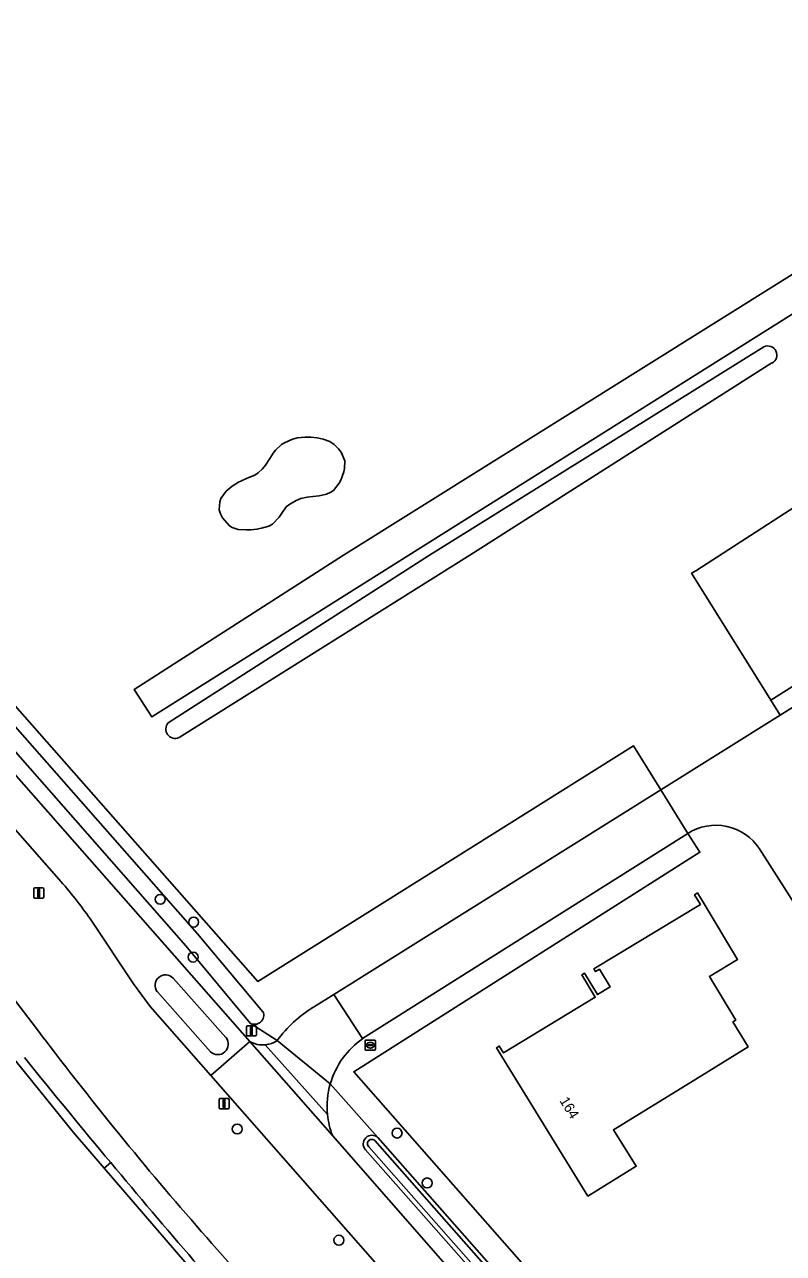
# Model space of a CAD drawing. Extents: x 156061 to 157804, y 383437 to 385640.
# Drawn here: x 157310.1 to 157384.8, y 384181.3 to 384302.2 of the extents above; entities that cross this region are included whole.
import ezdxf

# ---------------------------------------------------------------- set-up
doc = ezdxf.new("R2010")
doc.units = 0
for name, color, linetype in [('IMGEO_Berm_groen', 7, 'Continuous'), ('IMGEO_Boom', 7, 'Continuous'), ('IMGEO_Fietspad_gesloten', 7, 'Continuous'), ('IMGEO_Groenvoorziening', 7, 'Continuous'), ('IMGEO_Hek', 7, 'Continuous'), ('IMGEO_Lichtmast', 7, 'Continuous'), ('IMGEO_Oever', 7, 'Continuous'), ('IMGEO_Pand', 7, 'Continuous'), ('IMGEO_Pand_nummerreeks', 7, 'Continuous'), ('IMGEO_Parkeervlak_open', 7, 'Continuous'), ('IMGEO_Rijbaan_lokaal_gesloten', 7, 'Continuous'), ('IMGEO_Rijbaan_lokaal_open', 7, 'Continuous'), ('IMGEO_Rioolput', 7, 'Continuous'), ('IMGEO_Terreindeel_zand', 7, 'Continuous'), ('IMGEO_Verkeersbordpaal', 7, 'Continuous'), ('IMGEO_Verkeerseiland_open', 7, 'Continuous'), ('IMGEO_Voetpad_gesloten', 7, 'Continuous'), ('IMGEO_Waterloop', 7, 'Continuous')]:
    doc.layers.add(name, color=color, linetype=linetype)

msp = doc.modelspace()

# ---------------------------------------------------------------- linework, layer by layer
at = {"layer": 'IMGEO_Berm_groen'}
for points in [[(157236.85, 384312.33), (157218.46, 384333.49), (157218.41, 384333.56), (157168.13, 384391.67), (157166.48, 384390.53), (157253.43, 384291.77), (157290.16, 384250), (157332.28, 384202.11)], [(157313.49, 384218.11), (157285.45, 384250), (157250.85, 384289.34), (157163.6, 384388.4), (157154.3, 384381.75), (157154.84, 384381.16), (157155.5, 384381.77), (157245.11, 384280.12), (157271.96, 384250), (157283.55, 384237)], [(157334.99, 384202.22), (157332.31, 384203.93), (157326, 384211.55), (157292.2, 384250), (157280.67, 384263.01), (157263.72, 384282.59), (157236.85, 384312.33)], [(157342.96, 384182.28), (157328.46, 384198.78), (157322.49, 384205.56), (157320.85, 384207.79), (157316.61, 384214.17)], [(157344.9, 384192.66), (157340.2, 384197.97)], [(157340.41, 384192.86), (157351.29, 384180.48), (157461.84, 384054.56), (157463.91, 384056.38), (157463.38, 384056.98), (157462.83, 384056.5), (157343.68, 384191.47)], [(157318.6, 384190.2), (157317.96, 384189.64), (157344.19, 384159.18), (157364.55, 384136), (157393.61, 384102.92), (157399.11, 384096.66), (157446.05, 384043.69), (157456.41, 384032.18), (157483.79, 384000), (157500, 383980.87), (157519.27, 383957.9), (157520.38, 383958.3), (157500, 383982.12), (157484.69, 384000), (157449.42, 384041.22), (157450.46, 384042.19), (157447.97, 384045.05), (157446.91, 384044.08), (157389.32, 384108.91), (157390.82, 384110.23), (157391.84, 384111.13), (157448.89, 384045.9), (157456.76, 384052.82), (157342.96, 384182.28)]]:
    msp.add_lwpolyline(points, dxfattribs=at)
for centre, radius, start, end in [((156899.34, 383891.57), 516.66, 36.9691, 41.9576), ((157282.68, 384190.52), 41.35, 34.8854, 41.8577), ((157602.88, 384423.61), 365.4, 217.2792, 219.3769), ((157333.54, 384204.41), 2.62, 241.3507, 275.9719), ((157333.54, 384204.41), 2.63, 276.0213, 303.5695), ((157348.05, 384195.74), 8.16, 164.1263, 185.543), ((157348.05, 384195.72), 8.15, 185.4292, 200.5441), ((157344.3, 384192.04), 0.853, 45.9281, 222.4567), ((157599.37, 384420.91), 360.98, 219.399, 223.387), ((157895.42, 384671.13), 751.01, 219.81993, 221.75138)]:
    msp.add_arc(centre, radius, start, end, dxfattribs=at)
at = {"layer": 'IMGEO_Boom'}
for centre in [(157323.47, 384216.12), (157326.76, 384213.88), (157326.71, 384210.43), (157331.05, 384193.51), (157346.78, 384193.11), (157349.74, 384188.2), (157341.05, 384182.56)]:
    msp.add_circle(centre, 0.489, dxfattribs=at)
at = {"layer": 'IMGEO_Fietspad_gesloten'}
for points in [[(156945.58, 384638.24), (156948.92, 384634.34), (156956.8, 384625), (156966.54, 384613.57), (156977.24, 384601.18), (156992.9, 384582.99), (157000, 384574.89), (157056.89, 384509.94), (157058.63, 384507.87), (157065.54, 384500), (157136.46, 384419.32), (157161.96, 384390.33), (157163.6, 384388.4), (157250.85, 384289.34), (157285.45, 384250), (157313.49, 384218.11)], [(157316.61, 384214.17), (157320.85, 384207.79), (157322.49, 384205.56), (157328.46, 384198.78), (157332.28, 384202.11), (157290.16, 384250), (157253.43, 384291.77), (157166.48, 384390.53), (157164.88, 384392.32), (157139.19, 384421.58)], [(157324.75, 384208.36), (157329.94, 384202.51)], [(157328.41, 384201.12), (157323.19, 384207.02)]]:
    msp.add_lwpolyline(points, dxfattribs=at)
for centre, radius, start, end in [((157282.68, 384190.52), 41.35, 34.8854, 41.8577), ((157323.99, 384207.66), 1.03, 42.9772, 218.4553), ((157329.13, 384201.87), 1.04, 226.0226, 38.4206)]:
    msp.add_arc(centre, radius, start, end, dxfattribs=at)
at = {"layer": 'IMGEO_Groenvoorziening'}
for points in [[(157148.09, 384418.78), (157168.34, 384395.15), (157168.77, 384395.5), (157170.61, 384393.4), (157170.15, 384393.08), (157199.06, 384360.03), (157296.11, 384250), (157333.07, 384208.04), (157370.06, 384231.22), (157372.73, 384226.9), (157384.48, 384234.26), (157383.56, 384235.74), (157375.77, 384248.22), (157376.17, 384248.48), (157394.08, 384260.05), (157409.63, 384270.1), (157417.93, 384257.27), (157401.72, 384247.12), (157402.65, 384245.64), (157409.61, 384250), (157420.5, 384257)], [(157338.54, 384205.49), (157340.57, 384206.76), (157372.73, 384226.9), (157370.06, 384231.22), (157333.07, 384208.04), (157296.11, 384250), (157199.06, 384360.03), (157170.15, 384393.08), (157168.15, 384391.68), (157168.13, 384391.67), (157218.41, 384333.56)], [(157281.33, 384234.83), (157268.18, 384250), (157243.45, 384278.53), (157154.04, 384380.42), (157154.84, 384381.16), (157154.3, 384381.75), (157152.75, 384380.64), (157157.1, 384375.67), (157214.42, 384310.24), (157233.65, 384288.31), (157235.49, 384286.21), (157267.06, 384250), (157294.3, 384218.6), (157310.23, 384198.96), (157314.94, 384193.15), (157317.96, 384189.64), (157318.6, 384190.2)], [(157219.37, 384334.3), (157227.36, 384325.53), (157240.21, 384310.93), (157250.68, 384299.53), (157286.73, 384258.96), (157294.33, 384250), (157327.15, 384212.74), (157333.58, 384205.06)], [(157422.28, 384264.72), (157416.27, 384274.39), (157438.11, 384288.09), (157430, 384300.64), (157429.54, 384301.35), (157347.95, 384250), (157322.66, 384234.08), (157320.89, 384236.78), (157341.5, 384250), (157450.86, 384318.47), (157453.06, 384323.75), (157457.3, 384326.36)], [(157375.38, 384222.59), (157376.59, 384220.76), (157342.51, 384199.14), (157412.58, 384119.43), (157466.22, 384058.41), (157468.2, 384056.16), (157486.53, 384035.35), (157490.12, 384031.28), (157495.9, 384024.71), (157497.66, 384025.67), (157500, 384027.19), (157642, 384119.41), (157643.26, 384117.4), (157752.8, 384188.65), (157752.54, 384194.33), (157751.65, 384205.4), (157750.08, 384220.37), (157749.32, 384226.2), (157748.06, 384232.65), (157745.14, 384247.49), (157743.64, 384254.59), (157738.42, 384274.55), (157728.47, 384313.42)], [(157435.58, 384300.77), (157435.68, 384298.54), (157441.16, 384290.01), (157442.6, 384290.91), (157453.76, 384273.49), (157468.36, 384250), (157480.13, 384231.06), (157405.83, 384184.39), (157382.46, 384221.08)], [(157446.05, 384043.69), (157399.11, 384096.66), (157393.61, 384102.92), (157364.55, 384136), (157344.19, 384159.18), (157317.96, 384189.64), (157314.94, 384193.15), (157310.23, 384198.96), (157294.3, 384218.6), (157267.06, 384250), (157235.49, 384286.21)], [(157324.26, 384233.49), (157349.96, 384250), (157382.88, 384270.52)], [(157383.67, 384268.93), (157353.95, 384250), (157325.32, 384232.04)], [(157340.2, 384197.97), (157344.9, 384192.66), (157463.98, 384057.5), (157463.38, 384056.98), (157463.91, 384056.38), (157466.22, 384058.41), (157412.58, 384119.43), (157342.51, 384199.14), (157376.59, 384220.76), (157375.38, 384222.59), (157343.39, 384202.41)], [(157332.31, 384203.93), (157334.99, 384202.22)]]:
    msp.add_lwpolyline(points, dxfattribs=at)
for points in [[(157332.02, 384257.58), (157332.77, 384257.88), (157333.1, 384258.1), (157333.55, 384258.52), (157333.83, 384258.88), (157334.25, 384259.52), (157334.57, 384260.04), (157334.81, 384260.36), (157335.41, 384260.9), (157335.69, 384261.08), (157336.5, 384261.43), (157336.99, 384261.55), (157337.69, 384261.63), (157338.3, 384261.63), (157338.9, 384261.57), (157339.51, 384261.44), (157340.15, 384261.19), (157340.58, 384260.91), (157341.03, 384260.48), (157341.27, 384260.16), (157341.64, 384259.28), (157341.6, 384258.55), (157341.53, 384258.22), (157341.23, 384257.39), (157341.07, 384257.09), (157340.51, 384256.38), (157340.26, 384256.21), (157339.82, 384256.02), (157339.1, 384255.85), (157338.5, 384255.78), (157337.92, 384255.71), (157337.31, 384255.57), (157336.84, 384255.39), (157336.21, 384255.04), (157335.88, 384254.76), (157335.43, 384254.13), (157335.19, 384253.76), (157334.52, 384253.07), (157334.16, 384252.87), (157333.45, 384252.65), (157332.98, 384252.56), (157332.38, 384252.5), (157331.93, 384252.49), (157331.14, 384252.55), (157330.55, 384252.73), (157330.28, 384252.88), (157329.59, 384253.69), (157329.39, 384254.08), (157329.27, 384254.46), (157329.33, 384255.27), (157329.45, 384255.57), (157329.97, 384256.3), (157330.55, 384256.8), (157331.17, 384257.2), (157331.46, 384257.34)], [(157377.52, 384208.52), (157380.11, 384204.23), (157379.83, 384204.05), (157381.32, 384201.59), (157375.67, 384198.1), (157368.09, 384193.43), (157370.31, 384189.84), (157365.56, 384186.91), (157356.56, 384201.5), (157356.84, 384201.67), (157357.24, 384201.01), (157366.28, 384206.48), (157364.95, 384208.68), (157365.23, 384208.85), (157366.5, 384206.75), (157367.74, 384207.5), (157366.7, 384209.24), (157366.32, 384209.01), (157366.15, 384209.29), (157376.63, 384215.62), (157376.06, 384216.58), (157376.34, 384216.75), (157376.99, 384215.67), (157380.29, 384210.2)]]:
    msp.add_lwpolyline(points, close=True, dxfattribs=at)
for centre, radius, start, end in [((157383.27, 384269.72), 0.888, 296.1463, 116.0599), ((157324.94, 384232.88), 0.919, 138.349, 294.001), ((157378.16, 384218.3), 5.12, 32.8794, 122.899), ((157344.97, 384194.97), 12.34, 121.4303, 143.9831), ((157332.76, 384204.71), 0.895, 239.575, 23.5188), ((157348.15, 384195.63), 8.28, 125.0321, 163.6151), ((157900.4, 384675.33), 757.53, 218.81105, 219.82262)]:
    msp.add_arc(centre, radius, start, end, dxfattribs=at)
at = {"layer": 'IMGEO_Hek'}
for points in [[(157372.73, 384226.9), (157370.06, 384231.22), (157333.07, 384208.04), (157296.11, 384250)], [(157375.38, 384222.59), (157372.73, 384226.9)], [(157376.59, 384220.76), (157342.51, 384199.14), (157412.58, 384119.43), (157466.22, 384058.41)]]:
    msp.add_lwpolyline(points, dxfattribs=at)
at = {"layer": 'IMGEO_Lichtmast'}
for p, q in [((157311.02, 384216.34), (157311.02, 384217.14)), ((157311.02, 384217.14), (157311.02, 384216.34)), ((157311.12, 384217.24), (157311.9, 384217.24)), ((157311.9, 384217.24), (157311.12, 384217.24)), ((157311.9, 384216.24), (157311.12, 384216.24)), ((157311.12, 384216.24), (157311.9, 384216.24)), ((157312, 384217.14), (157312, 384216.34)), ((157312, 384216.34), (157312, 384217.14)), ((157329.26, 384195.6), (157329.26, 384196.4)), ((157329.26, 384196.4), (157329.26, 384195.6)), ((157329.36, 384196.5), (157330.15, 384196.5)), ((157330.15, 384196.5), (157329.36, 384196.5)), ((157330.25, 384196.4), (157330.25, 384195.6)), ((157330.25, 384195.6), (157330.25, 384196.4)), ((157330.15, 384195.5), (157329.36, 384195.5)), ((157329.36, 384195.5), (157330.15, 384195.5))]:
    msp.add_line(p, q, dxfattribs=at)
for points in [[(157311.43, 384217.12), (157311.59, 384217.12), (157311.59, 384216.37), (157311.43, 384216.37), (157311.43, 384217.12)], [(157329.68, 384196.38), (157329.83, 384196.38), (157329.83, 384195.63), (157329.68, 384195.63), (157329.68, 384196.38)]]:
    msp.add_lwpolyline(points, dxfattribs=at)
for centre, start, end in [((157311.12, 384217.14), 90, 180), ((157311.12, 384217.14), 90, 180), ((157311.12, 384216.34), 180, 270), ((157311.12, 384216.34), 180, 270), ((157311.9, 384217.14), 0, 90), ((157311.9, 384217.14), 360, 90), ((157311.9, 384216.34), 270, 0), ((157311.9, 384216.34), 270, 0), ((157329.36, 384196.4), 90, 180), ((157329.36, 384196.4), 90, 180), ((157329.36, 384195.6), 180, 270), ((157329.36, 384195.6), 180, 270), ((157330.15, 384196.4), 0, 90), ((157330.15, 384196.4), 360, 90), ((157330.15, 384195.6), 270, 0), ((157330.15, 384195.6), 270, 0)]:
    msp.add_arc(centre, 0.1, start, end, dxfattribs=at)
at = {"layer": 'IMGEO_Oever'}
for points in [[(157343.68, 384191.47), (157462.83, 384056.5), (157463.38, 384056.98), (157463.98, 384057.5), (157344.9, 384192.66)], [(157344.59, 384192.37), (157463.38, 384057.54), (157463.1, 384057.3), (157462.87, 384057.1), (157385.2, 384145.03), (157343.99, 384191.76)]]:
    msp.add_lwpolyline(points, dxfattribs=at)
for centre, radius, start, end in [((157344.3, 384192.04), 0.853, 45.9281, 222.4567), ((157344.29, 384192.06), 0.429, 45.2195, 225.3478)]:
    msp.add_arc(centre, radius, start, end, dxfattribs=at)
at = {"layer": 'IMGEO_Pand'}
msp.add_lwpolyline([(157379.83, 384204.05), (157380.11, 384204.23), (157377.52, 384208.52), (157380.29, 384210.2), (157376.99, 384215.67), (157376.34, 384216.75), (157376.06, 384216.58), (157376.63, 384215.62), (157366.15, 384209.29), (157366.32, 384209.01), (157366.7, 384209.24), (157367.74, 384207.5), (157366.5, 384206.75), (157365.23, 384208.85), (157364.95, 384208.68), (157366.28, 384206.48), (157357.24, 384201.01), (157356.84, 384201.67), (157356.56, 384201.5), (157365.56, 384186.91), (157370.31, 384189.84), (157368.09, 384193.43), (157375.67, 384198.1), (157381.32, 384201.59)], close=True, dxfattribs=at)
at = {"layer": 'IMGEO_Parkeervlak_open'}
for points in [[(157382.46, 384221.08), (157405.83, 384184.39), (157480.13, 384231.06), (157468.36, 384250), (157453.76, 384273.49)], [(157420.5, 384257), (157409.61, 384250), (157402.65, 384245.64), (157401.03, 384244.62), (157388.51, 384236.78), (157384.48, 384234.26), (157372.73, 384226.9), (157375.38, 384222.59)]]:
    msp.add_lwpolyline(points, dxfattribs=at)
msp.add_lwpolyline([(157383.56, 384235.74), (157387.58, 384238.26), (157400.1, 384246.1), (157401.72, 384247.12), (157417.93, 384257.27), (157409.63, 384270.1), (157394.08, 384260.05), (157376.17, 384248.48), (157375.77, 384248.22)], close=True, dxfattribs=at)
msp.add_arc((157378.16, 384218.3), 5.12, 32.8794, 122.899, dxfattribs=at)
at = {"layer": 'IMGEO_Rijbaan_lokaal_gesloten'}
msp.add_lwpolyline([(157461.84, 384054.56), (157351.29, 384180.48), (157340.41, 384192.86), (157332.28, 384202.11), (157328.46, 384198.78), (157342.96, 384182.28), (157456.76, 384052.82)], dxfattribs=at)
at = {"layer": 'IMGEO_Rijbaan_lokaal_open'}
for points in [[(157457.3, 384326.36), (157453.06, 384323.75), (157450.86, 384318.47), (157341.5, 384250), (157320.89, 384236.78), (157322.66, 384234.08), (157347.95, 384250), (157429.54, 384301.35), (157430, 384300.64), (157436.8, 384305.03), (157437.24, 384305.85), (157437.84, 384306.57), (157456.79, 384318.5), (157458.11, 384316.49), (157462.66, 384309.61), (157468.04, 384313.11), (157465.07, 384317.8)], [(157343.39, 384202.41), (157340.57, 384206.76), (157338.54, 384205.49)], [(157332.28, 384202.11), (157340.41, 384192.86)], [(157333.81, 384201.8), (157339.93, 384194.95)], [(157339.93, 384194.95), (157333.81, 384201.8)], [(157334.99, 384202.22), (157340.2, 384197.97)], [(157340.2, 384197.97), (157334.99, 384202.22)]]:
    msp.add_lwpolyline(points, dxfattribs=at)
msp.add_lwpolyline([(157340.57, 384206.76), (157343.39, 384202.41), (157375.38, 384222.59), (157372.73, 384226.9)], close=True, dxfattribs=at)
for centre, radius, start, end in [((157344.97, 384194.97), 12.34, 121.4303, 143.9831), ((157333.54, 384204.41), 2.62, 241.3507, 275.9719), ((157333.54, 384204.41), 2.63, 276.0213, 303.5695), ((157348.15, 384195.63), 8.28, 125.0321, 163.6151), ((157348.05, 384195.74), 8.16, 164.1263, 185.543), ((157348.05, 384195.72), 8.15, 185.4292, 200.5441)]:
    msp.add_arc(centre, radius, start, end, dxfattribs=at)
at = {"layer": 'IMGEO_Rioolput'}
for p, q in [((157343.64, 384201.34), (157343.64, 384202.19)), ((157343.71, 384202.26), (157344.57, 384202.26)), ((157343.9, 384201.76), (157343.9, 384201.77)), ((157343.94, 384201.81), (157344.34, 384201.81)), ((157344.34, 384201.72), (157343.94, 384201.72)), ((157344.13, 384202.04), (157344.15, 384202.04)), ((157344.38, 384201.77), (157344.38, 384201.76)), ((157344.64, 384202.19), (157344.64, 384201.34)), ((157344.57, 384201.26), (157343.71, 384201.26)), ((157344.15, 384201.48), (157344.12, 384201.48))]:
    msp.add_line(p, q, dxfattribs=at)
for points in [[(157343.64, 384201.34), (157343.64, 384202.19)], [(157343.71, 384202.26), (157344.57, 384202.26)], [(157344.64, 384202.19), (157344.64, 384201.34)], [(157344.57, 384201.26), (157343.71, 384201.26)]]:
    msp.add_lwpolyline(points, dxfattribs=at)
for centre, radius, start, end in [((157343.72, 384202.19), 0.0765, 91.552, 178.448), ((157343.72, 384202.19), 0.0765, 91.552, 178.448), ((157343.94, 384201.77), 0.0403, 85.8775, 175.7526), ((157343.93, 384201.76), 0.0366, 178.938, 274.7102), ((157344.34, 384201.77), 0.0386, 1.7309, 96.639), ((157344.34, 384201.76), 0.043, 264.8664, 352.4533), ((157344.56, 384202.19), 0.0765, 1.552, 88.448), ((157344.56, 384202.19), 0.0765, 1.552, 88.448), ((157343.72, 384201.34), 0.0765, 181.552, 268.448), ((157343.72, 384201.34), 0.0765, 181.552, 268.448), ((157344.56, 384201.34), 0.0765, 271.552, 358.448), ((157344.56, 384201.34), 0.0765, 271.552, 358.448)]:
    msp.add_arc(centre, radius, start, end, dxfattribs=at)
for centre, major_axis, ratio, start_param, end_param in [((157344.13, 384201.76), (-0.387, 0.002), 0.722429, 4.712389, 7.853982), ((157344.15, 384201.76), (-0.39, 0.002), 0.717154, 1.570796, 4.712389)]:
    msp.add_ellipse(centre, major_axis=major_axis, ratio=ratio, start_param=start_param, end_param=end_param, dxfattribs=at)
at = {"layer": 'IMGEO_Terreindeel_zand'}
msp.add_lwpolyline([(157332.02, 384257.58), (157331.46, 384257.34), (157331.17, 384257.2), (157330.55, 384256.8), (157329.97, 384256.3), (157329.45, 384255.57), (157329.33, 384255.27), (157329.27, 384254.46), (157329.39, 384254.08), (157329.59, 384253.69), (157330.28, 384252.88), (157330.55, 384252.73), (157331.14, 384252.55), (157331.93, 384252.49), (157332.38, 384252.5), (157332.98, 384252.56), (157333.45, 384252.65), (157334.16, 384252.87), (157334.52, 384253.07), (157335.19, 384253.76), (157335.43, 384254.13), (157335.88, 384254.76), (157336.21, 384255.04), (157336.84, 384255.39), (157337.31, 384255.57), (157337.92, 384255.71), (157338.5, 384255.78), (157339.1, 384255.85), (157339.82, 384256.02), (157340.26, 384256.21), (157340.51, 384256.38), (157341.07, 384257.09), (157341.23, 384257.39), (157341.53, 384258.22), (157341.6, 384258.55), (157341.64, 384259.28), (157341.27, 384260.16), (157341.03, 384260.48), (157340.58, 384260.91), (157340.15, 384261.19), (157339.51, 384261.44), (157338.9, 384261.57), (157338.3, 384261.63), (157337.69, 384261.63), (157336.99, 384261.55), (157336.5, 384261.43), (157335.69, 384261.08), (157335.41, 384260.9), (157334.81, 384260.36), (157334.57, 384260.04), (157334.25, 384259.52), (157333.83, 384258.88), (157333.55, 384258.52), (157333.1, 384258.1), (157332.77, 384257.88)], close=True, dxfattribs=at)
at = {"layer": 'IMGEO_Verkeersbordpaal'}
for p, q in [((157331.95, 384202.78), (157331.95, 384203.58)), ((157331.95, 384203.58), (157331.95, 384202.78)), ((157332.05, 384203.68), (157332.84, 384203.68)), ((157332.84, 384203.68), (157332.05, 384203.68)), ((157332.94, 384203.58), (157332.94, 384202.78)), ((157332.94, 384202.78), (157332.94, 384203.58)), ((157332.84, 384202.68), (157332.05, 384202.68)), ((157332.05, 384202.68), (157332.84, 384202.68))]:
    msp.add_line(p, q, dxfattribs=at)
msp.add_lwpolyline([(157332.37, 384203.55), (157332.52, 384203.55), (157332.52, 384202.8), (157332.37, 384202.8), (157332.37, 384203.55)], dxfattribs=at)
for centre, start, end in [((157332.05, 384203.58), 90, 180), ((157332.05, 384203.58), 90, 180), ((157332.84, 384203.58), 0, 90), ((157332.84, 384203.58), 360, 90), ((157332.05, 384202.78), 180, 270), ((157332.05, 384202.78), 180, 270), ((157332.84, 384202.78), 270, 0), ((157332.84, 384202.78), 270, 0)]:
    msp.add_arc(centre, 0.1, start, end, dxfattribs=at)
at = {"layer": 'IMGEO_Verkeerseiland_open'}
for points in [[(157329.94, 384202.51), (157324.75, 384208.36)], [(157323.19, 384207.02), (157328.41, 384201.12)]]:
    msp.add_lwpolyline(points, dxfattribs=at)
for centre, radius, start, end in [((157323.99, 384207.66), 1.03, 42.9772, 218.4553), ((157329.13, 384201.87), 1.04, 226.0226, 38.4206)]:
    msp.add_arc(centre, radius, start, end, dxfattribs=at)
at = {"layer": 'IMGEO_Voetpad_gesloten'}
msp.add_lwpolyline([(157388.51, 384236.78), (157387.58, 384238.26), (157383.56, 384235.74), (157384.48, 384234.26)], close=True, dxfattribs=at)
at = {"layer": 'IMGEO_Waterloop'}
for points in [[(157218.41, 384333.56), (157218.46, 384333.49), (157236.85, 384312.33), (157263.72, 384282.59), (157280.67, 384263.01), (157292.2, 384250), (157326, 384211.55), (157332.31, 384203.93)], [(157333.58, 384205.06), (157327.15, 384212.74), (157294.33, 384250), (157286.73, 384258.96), (157250.68, 384299.53)], [(157382.88, 384270.52), (157349.96, 384250), (157324.26, 384233.49)], [(157325.32, 384232.04), (157353.95, 384250), (157383.67, 384268.93)], [(157343.99, 384191.76), (157385.2, 384145.03), (157462.87, 384057.1), (157463.1, 384057.3), (157463.38, 384057.54), (157344.59, 384192.37)]]:
    msp.add_lwpolyline(points, dxfattribs=at)
for centre, radius, start, end in [((157383.27, 384269.72), 0.888, 296.1463, 116.0599), ((156899.34, 383891.57), 516.66, 36.9691, 41.9576), ((157324.94, 384232.88), 0.919, 138.349, 294.001), ((157332.76, 384204.71), 0.895, 239.575, 23.5188), ((157602.88, 384423.61), 365.4, 217.2792, 219.3769), ((157900.4, 384675.33), 757.53, 218.81105, 219.82262), ((157344.29, 384192.06), 0.429, 45.2195, 225.3478), ((157599.37, 384420.91), 360.98, 219.399, 223.387), ((157895.42, 384671.13), 751.01, 219.81993, 221.75138)]:
    msp.add_arc(centre, radius, start, end, dxfattribs=at)

# ---------------------------------------------------------------- texts
at = {"layer": 'IMGEO_Pand_nummerreeks'}
msp.add_text('164', height=1, rotation=301.6557, dxfattribs=at).set_placement((157362.73, 384196.3))

doc.saveas('drawing.dxf')
